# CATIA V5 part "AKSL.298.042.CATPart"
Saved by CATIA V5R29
Part number: АКСЛ.298.042
Definition: Уголок 500 мм
Publications: "Грань по длине шипа", "Грань по ширине шипа"
Material "Steel": density 7860 kg/m3, Young's modulus 2e+11 Pa, Poisson ratio 0.266, thermal expansion 1.17e-05 1/K
Bounding box of the stored display mesh (mm): x -250 to 250, y -51 to 52, z -51 to 52
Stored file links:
  Z:\ООО Аксель\Соединения бруса\Соединения бруса\Соединения из листа\АКСЛ.298.040 (Кватро)\AKSL.298.042.CATPart
  Z:\ООО Аксель\Соединения бруса\Соединения бруса\Соединения из листа\АКСЛ.298.040 (Кватро)\AKSL.298.040.CATProduct
  Z:\#Catalog_GosNIIAS\Holes&Pockets\Part\Соединение шип-паз\Ship-Paz.CATPart
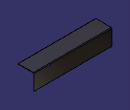
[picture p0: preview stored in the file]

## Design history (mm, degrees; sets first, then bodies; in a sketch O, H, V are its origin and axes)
External parameters (linked from other documents)
  `External.S металла` = 2 mm
  `External.R гиба` = 1.9 mm
  `External.K factor` = 0.49
SheetMetalParameters1: Thickness 2 {= `External.S металла`}, BendRadius 1.9 {= `External.R гиба`}, KFactor 0.49 {= `External.K factor`}, ReliefRadialLength 1, ReliefAxialLength 2, MinimumBendRadius 0
Set1 "Шип в центре грани"
  Extract1 "Плоскость шипа": ExtractElem face of Wall1
  Extract2 "Грань по длине шипа": ExtractElem edge of Extract1
  Extract3 "Грань по ширине шипа": ExtractElem edge of Extract1
Set2
  DatumSurface1: linked copy from another document
  DatumCurve1: linked copy from another document
  DatumCurve2: linked copy from another document
Body1 (main body)
  ThickSurface1: BotOffset 0, Surface DatumSurface1, TopOffset 2 {= `External.S металла`}
  Recognize1: Recognize_BendTable SheetMetalParameters1, Recognize_ReferenceFace face of ThickSurface1, Recognize_BendDefaultRadius 1.9 {= `External.R гиба`}, KFacteur 0.49 {= SheetMetalParameters1.KFactor}
  d_Bend1: Bend_BendTable SheetMetalParameters1, Bend_Thickness 2 {= `External.S металла`}, Bend_KFactor 0.49 {= SheetMetalParameters1.KFactor}, Bend_FirstSupport face of Recognize1, Bend_SecondSupport face of Recognize1, Bend_KFactorRadius 1.9 {= d_Bend1.CylindricalBendSurf_Radius}, Bend_Deduction -3.2761 {= (d_Bend1.CylindricalBendSurf_Radius+SheetMetalParameters1.Thickness*d_Bend1.Bend_KFactor)*(PI-abs(d_Bend1.BendSurf_OpenAngle))-2*(d_Bend1.CylindricalBendSurf_Radius+SheetMetalParameters1.Thickness)*tan(min((PI-abs(d_Bend1.BendSurf_OpenAngle)),(PI/2))/2)}
  Wall1: Thickness 2 {= `External.S металла`}, Profile Sketch2, ListTangentTo face of Recognize1, OffsetValue 0
  CutOut1: Direction Sketch3, EndLimit through (limit type 2), Orientation true, Profile Sketch3, StartLimit through (limit type 2)
  CutOut2: Direction Sketch1, EndLimit through (limit type 2), Orientation true, Profile Sketch1, StartLimit through (limit type 2), Thickness1 2, Thickness2 2
  SHM_Mirror1: MirroringPlane yz-plane, ObjectToMirror CutOut2
  Sketch1 on face of Recognize1, origin (0, 52, 0), H (-1, 0, 0), V (0, 0, 1)
    reference projected line E1 (240.5, -50) -> (240.5, -52) from edge [face of CutOut1 | face of Recognize1]
    line L1 (250, -52) -> (240.5, -52)
    line L2 (240.5, -52) -> (240.5, -51)
    line L3 (240.5, -51) -> (250, -51)
    line L4 (250, -51) -> (250, -52)
    point P8 (240.5, -51)
    horizontal: L1 H, L3 H
    vertical: L2 V, L4 V
    midpoint: P8 E1
  Sketch2 on face of Recognize1, origin (-52, 0, 52), H (0, -1, 0), V (1, 0, 0)
    reference projected line E1 (50, 302) -> (50, -198) from edge [face of Recognize1 | face of Recognize1]
    line L1 (51, -188) -> (50, -188)
    line L2 (50, -188) -> (50, 292)
    line L3 (50, 292) -> (51, 292)
    line L4 (51, 292) -> (51, -188)
    axis line L5 (50, 52) -> (51, 52)
    point P7 (50, 52)
    point P8 (51, 52)
    distance L2 L4 = 1 {= `External.S металла` /2}
    distance L1 L3 = 480
    length E1 = 500 (reference)
    perpendicularity: L2 L1
    midpoint: P7 L2, P8 L4, P7 E1
    coincidence: L2 E1
  Sketch3 on DatumCurve1, origin (-240, 51, -50), H (1, 0, 0), V (0, 0, -1)
    reference projected line E1 (0, 0) -> (0, 2) from DatumCurve2
    reference projected line E2 (0, 0) -> (480, 0) from DatumCurve1
    construction line L1 (0, 1) -> (240, 1)
    point P5 (0, 1)
    point P6 (240, 1)
    axis line L2 (240, 0) -> (240, 7.3468)
    point P7 (240, 0)
    line L3 (480.5, 2) -> (480.5, 0)
    line L4 (480.5, 0) -> (-0.5, 0)
    line L5 (-0.5, 0) -> (-0.5, 2)
    line L6 (-0.5, 2) -> (480.5, 2)
    distance L5 E1 = 0.5
    distance E2 L4 = 0
    midpoint: P5 E1, P7 E2
    coincidence: L2 P6
    equidistance: L3 L5 P6, L4 L6 P6
    parallelism: L1 E2, L2 E1, L6 L4, L3 L5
